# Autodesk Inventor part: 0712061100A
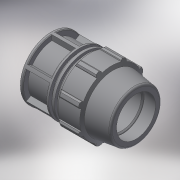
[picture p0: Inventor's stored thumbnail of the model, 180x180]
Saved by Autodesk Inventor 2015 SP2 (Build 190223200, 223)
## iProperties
Created: 2017-02
Part Number: 0712061100A
Material: Generic
Description: PLASSON END PLUG 110
Document SubType Name: Modeling
Designer: KIM
Mass: 947.017 g
Surface Area: 1382.98 cm^2
Volume: 947.017 cm^3
Density: 1 g/cm^3
Appearance: Default
Author: Кирилл
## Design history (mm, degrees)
derived "87120.ipt"
feature "Solid1::87120.ipt"
tag "TaggingFeature1"
body "Solid1"
other parameters: "d4" = 33, "d5" = 57.75, "d7" = 181, "d8" = 135.75, "d9" = 33, "d11" = 6.6, "d12" = 144.8, "d13" = 120 deg, "d14" = 143, "d15" = 8 deg, "d16" = 162.9, "d18" = 5.5, "d19" = 35 deg, "d20" = 17.5 deg, "d21" = 168.33, "d23" = 0, "d25" = 360 deg, "d27" = 3.62, "d34" = 9.05, "d36" = 0, "d42" = 57.75, "d43" = 5.43, "d46" = 3.3, "d53" = 2.2, "d55" = 360 deg, "d59" = 57.75, "d64" = 231, "d66" = 23.53, "d67" = 14.48, "d68" = 213, "d70" = 26.4, "d71" = 6.6, "d72" = 159.642, "d75" = 13.2, "E_" = 181, "H_" = 231, "l_" = 213
